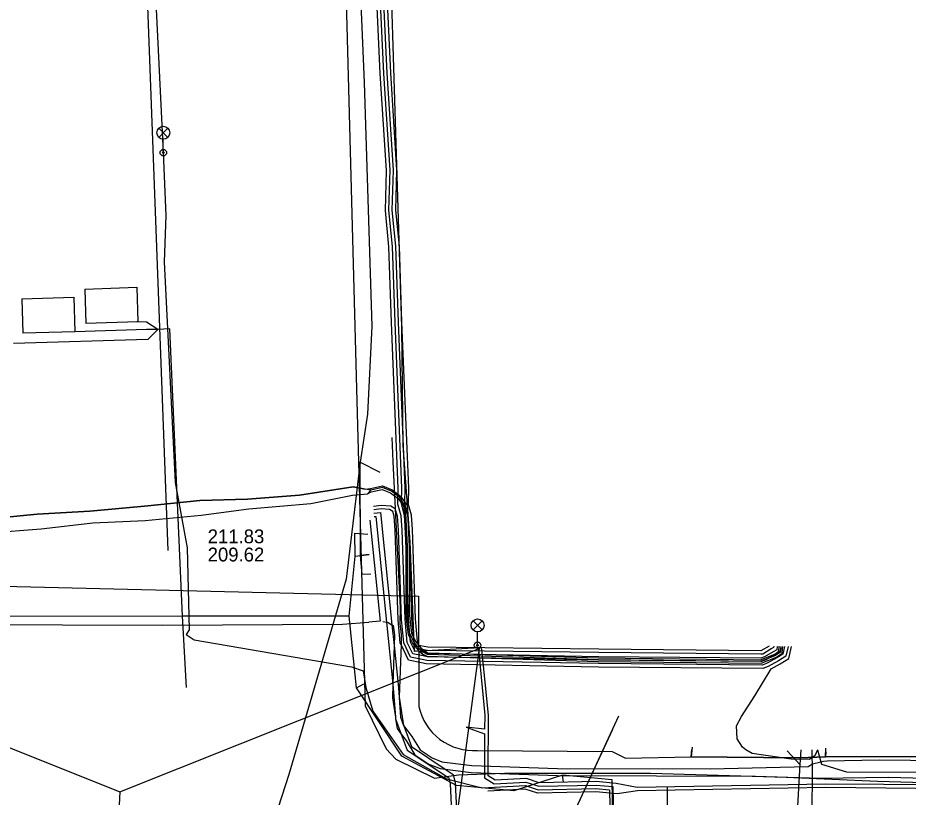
# Model space of a CAD drawing. Extents: x -596228 to -595156, y -1161235 to -1159373.
# Drawn here: x -595386.4 to -595334.9, y -1161026 to -1160980.9 of the extents above; entities that cross this region are included whole.
import ezdxf

# ---------------------------------------------------------------- set-up
doc = ezdxf.new("R2010")
doc.units = 0
for name, color, linetype in [('Vrstva 1', 7, 'Continuous'), ('Vrstva 12', 7, 'Continuous'), ('Vrstva 19', 7, 'Continuous'), ('Vrstva 33', 7, 'Continuous'), ('Vrstva 4', 7, 'Continuous'), ('Vrstva 42', 7, 'Continuous'), ('Vrstva 44', 7, 'Continuous'), ('Vrstva 54', 7, 'Continuous'), ('Vrstva 55', 7, 'Continuous'), ('Vrstva 58', 7, 'Continuous'), ('Vrstva 9', 7, 'Continuous')]:
    doc.layers.add(name, color=color, linetype=linetype)

msp = doc.modelspace()

# ---------------------------------------------------------------- linework, layer by layer
at = {"layer": 'Vrstva 1'}
for p, q in [((-595377.69, -1161011.68), (-595379.64, -1160959.52)), ((-595351.64, -1161021.26), (-595357.27, -1161033.42)), ((-595341.9, -1161023.27), (-595341.15, -1161024.06))]:
    msp.add_line(p, q, dxfattribs=at)
at = {"layer": 'Vrstva 12'}
for p in [(-595339.65, -1161023.32), (-595331.81, -1161023.6)]:
    msp.add_line(p, (-595339.67, -1161023.61), dxfattribs=at)
for points in [[(-595367.69, -1160963.36), (-595367.65, -1160963.76), (-595366.71, -1160969.68), (-595367.4, -1160979.92), (-595366.8, -1161002.33), (-595366.29, -1161020.66), (-595365.09, -1161023.16)], [(-595365.09, -1161023.16), (-595364.52, -1161023.76), (-595362.29, -1161024.86), (-595360.89, -1161024.66), (-595358.24, -1161024.57), (-595355.24, -1161024.57), (-595354.66, -1161024.57), (-595349.79, -1161024.56)], [(-595339.67, -1161023.61), (-595341.17, -1161023.67), (-595347.44, -1161023.62), (-595347.4, -1161023.2)], [(-595349.79, -1161024.56), (-595341.94, -1161024.8), (-595336.67, -1161025.03), (-595331.28, -1161025.18), (-595320.15, -1161025.06), (-595315.95, -1161025.06), (-595312.39, -1161025.22)]]:
    msp.add_lwpolyline(points, dxfattribs=at)
at = {"layer": 'Vrstva 19'}
for p, q in [((-595340.432, -1161024.484), (-595340.453, -1161023.206)), ((-595340.45, -1161026.84), (-595340.432, -1161024.484))]:
    msp.add_line(p, q, dxfattribs=at)
msp.add_lwpolyline([(-595348.81, -1161026.94), (-595348.817, -1161025.481), (-595348.816, -1161025.335)], dxfattribs=at)
at = {"layer": 'Vrstva 33'}
for p, q in [((-595378.235, -1160987.265), (-595377.705, -1160987.795)), ((-595378.235, -1160987.795), (-595377.705, -1160987.265)), ((-595377.97, -1160988.68), (-595377.97, -1160987.905)), ((-595360.059, -1161015.753), (-595359.529, -1161016.283)), ((-595360.059, -1161016.283), (-595359.529, -1161015.753)), ((-595359.794, -1161017.168), (-595359.794, -1161016.393))]:
    msp.add_line(p, q, dxfattribs=at)
for centre, radius in [((-595377.97, -1160987.53), 0.375), ((-595377.97, -1160988.68), 0.19), ((-595377.97, -1160988.68), 0.05), ((-595359.794, -1161016.018), 0.375), ((-595359.794, -1161017.168), 0.19), ((-595359.794, -1161017.168), 0.05)]:
    msp.add_circle(centre, radius, dxfattribs=at)
at = {"layer": 'Vrstva 42'}
for p, q in [((-595382.508, -1160996.565), (-595379.51, -1160996.467)), ((-595379.51, -1160996.467), (-595379.445, -1160998.466)), ((-595382.508, -1160996.565), (-595382.443, -1160998.564)), ((-595386.146, -1160997.129), (-595383.147, -1160997.04)), ((-595386.146, -1160997.129), (-595386.087, -1160999.128)), ((-595383.147, -1160997.04), (-595383.088, -1160999.039)), ((-595379.445, -1160998.466), (-595382.443, -1160998.564)), ((-595379.445, -1160998.466), (-595379.497, -1160998.468)), ((-595378.946, -1160998.48), (-595379.445, -1160998.466)), ((-595378.291, -1160998.903), (-595378.946, -1160998.48)), ((-595383.088, -1160999.039), (-595386.087, -1160999.128)), ((-595378.941, -1160998.912), (-595383.088, -1160999.039)), ((-595378.291, -1160998.903), (-595378.941, -1160998.912)), ((-595378.291, -1160998.903), (-595378.86, -1160999.477)), ((-595378.86, -1160999.477), (-595386.626, -1160999.714)), ((-595366.903, -1161010.68), (-595366.152, -1161010.751)), ((-595366.876, -1161012.022), (-595366.071, -1161011.924)), ((-595366.796, -1161019.625), (-595366.382, -1161019.402)), ((-595354.818, -1161025.09), (-595354.882, -1161024.669))]:
    msp.add_line(p, q, dxfattribs=at)
for points in [[(-595366.8, -1160974.13), (-595366.35, -1160984.63), (-595365.92, -1160998.71)], [(-595342.25, -1161017.23), (-595342.32, -1161017.55), (-595342.6, -1161017.72), (-595343.119, -1161018.012), (-595343.374, -1161018.11), (-595352.793, -1161018.03), (-595362.714, -1161017.84), (-595362.951, -1161017.786), (-595363.549, -1161017.671), (-595363.87, -1161016.999), (-595363.99, -1161015.666), (-595364.16, -1161010.505), (-595364.22, -1161009.677), (-595364.402, -1161009.01), (-595364.4, -1161008.922), (-595364.38, -1161008.093), (-595364.77, -1160998.501), (-595364.919, -1160994.12), (-595365.13, -1160992.021), (-595365.06, -1160989.705), (-595365.42, -1160984.107), (-595365.819, -1160975.572)], [(-595342.46, -1161017.23), (-595342.497, -1161017.424), (-595342.704, -1161017.549), (-595343.209, -1161017.832), (-595343.41, -1161017.91), (-595352.79, -1161017.83), (-595362.69, -1161017.64), (-595362.91, -1161017.59), (-595363.43, -1161017.49), (-595363.67, -1161016.981), (-595363.79, -1161015.654), (-595363.96, -1161010.495), (-595364.02, -1161009.663), (-595364.202, -1161008.99), (-595364.2, -1161008.927), (-595364.18, -1161008.091), (-595364.57, -1160998.494), (-595364.72, -1160994.107), (-595364.93, -1160992.014), (-595364.86, -1160989.702), (-595365.22, -1160984.096), (-595365.62, -1160975.551)], [(-595342.657, -1161017.221), (-595342.674, -1161017.297), (-595342.808, -1161017.378), (-595343.297, -1161017.679), (-595343.41, -1161017.69), (-595352.79, -1161017.59), (-595362.7, -1161017.47), (-595363.14, -1161017.39), (-595363.32, -1161017.35), (-595363.471, -1161016.963), (-595363.59, -1161015.642), (-595363.76, -1161010.484), (-595363.821, -1161009.648), (-595364.001, -1161008.97), (-595364, -1161008.933), (-595363.98, -1161008.089), (-595364.37, -1160998.486), (-595364.52, -1160994.093), (-595364.73, -1160992.006), (-595364.66, -1160989.698), (-595365.02, -1160984.084), (-595365.42, -1160975.529)], [(-595342.931, -1161017.218), (-595343.418, -1161017.49), (-595352.788, -1161017.39), (-595362.681, -1161017.27), (-595363.1, -1161017.194), (-595363.188, -1161017.174), (-595363.272, -1161016.945), (-595363.391, -1161015.629), (-595363.561, -1161010.474), (-595363.621, -1161009.634), (-595363.801, -1161008.965), (-595363.8, -1161008.938), (-595363.78, -1161008.088), (-595364.17, -1160998.479), (-595364.32, -1160994.08), (-595364.53, -1160991.999), (-595364.46, -1160989.695), (-595364.82, -1160984.073), (-595365.221, -1160975.508)], [(-595376.86, -1161015.49), (-595377.59, -1160998.875), (-595378.291, -1160998.903)], [(-595365.92, -1160998.71), (-595366.162, -1161003.793), (-595366.586, -1161006.586), (-595365.455, -1161007.152)], [(-595364.747, -1161005.146), (-595364.699, -1161006.547), (-595364.561, -1161009.281), (-595364.272, -1161014.986), (-595364.267, -1161015.003), (-595364.291, -1161015.907), (-595364.205, -1161016.543), (-595364.224, -1161017.126), (-595364.323, -1161020.175), (-595364.074, -1161021.801), (-595364.072, -1161021.814), (-595364.066, -1161021.822), (-595363.594, -1161022.451), (-595363.123, -1161023.221), (-595362.429, -1161023.683), (-595361.863, -1161023.905), (-595360.132, -1161024.126), (-595355.164, -1161024.292), (-595346.337, -1161024.321), (-595340.674, -1161024.173), (-595340.433, -1161024.029), (-595339.95, -1161023.906), (-595339.796, -1161023.867), (-595339.584, -1161023.858), (-595336.578, -1161023.801), (-595331.158, -1161023.852)], [(-595416.016, -1161006.14), (-595415.786, -1161006.15), (-595415.498, -1161006.235), (-595415.338, -1161006.482), (-595416.218, -1161013.623), (-595415.624, -1161014.085), (-595414.843, -1161014.3), (-595408.501, -1161014.826), (-595406.711, -1161015.033), (-595402.654, -1161015.522), (-595401.884, -1161015.7), (-595400.104, -1161016.11), (-595399.611, -1161016.162), (-595398.468, -1161016.036), (-595398.041, -1161016.049), (-595392.333, -1161016.113), (-595389.6, -1161015.959), (-595378.022, -1161015.998), (-595367.599, -1161015.944), (-595366.086, -1161015.828)], [(-595366.586, -1161006.586), (-595367.386, -1161013.351), (-595370.715, -1161024.634), (-595373.587, -1161033.521), (-595377.627, -1161052.858), (-595377.399, -1161059.852), (-595376.49, -1161070.471), (-595375.793, -1161073.227), (-595375.59, -1161076.931), (-595375.75, -1161078.662), (-595375.148, -1161080.228), (-595374.394, -1161084.227), (-595372.163, -1161100.132), (-595371.943, -1161102.902), (-595371.535, -1161104.379), (-595371.896, -1161105.915), (-595369.508, -1161121.937)], [(-595366.071, -1161011.923), (-595366.569, -1161011.967), (-595366.586, -1161006.586)], [(-595342.04, -1161017.23), (-595342.143, -1161017.676), (-595342.496, -1161017.891), (-595343.048, -1161018.199), (-595343.337, -1161018.311), (-595352.796, -1161018.23), (-595362.739, -1161018.039), (-595362.992, -1161017.982), (-595363.668, -1161017.852), (-595364.069, -1161017.017), (-595364.19, -1161015.678), (-595364.36, -1161010.516), (-595364.419, -1161009.692), (-595364.556, -1161009.284), (-595364.561, -1161009.281), (-595364.818, -1161009.122), (-595365.373, -1161009.08), (-595365.824, -1161009.141)], [(-595341.84, -1161017.24), (-595341.966, -1161017.803), (-595342.392, -1161018.062), (-595342.981, -1161018.387), (-595343.301, -1161018.511), (-595352.798, -1161018.43), (-595362.763, -1161018.239), (-595363.033, -1161018.177), (-595363.787, -1161018.032), (-595364.224, -1161017.126), (-595364.268, -1161017.035), (-595364.389, -1161015.691), (-595364.559, -1161010.526), (-595364.619, -1161009.706), (-595364.688, -1161009.437), (-595364.882, -1161009.318), (-595365.367, -1161009.281), (-595365.796, -1161009.339)], [(-595365.795, -1161009.521), (-595365.41, -1161009.481), (-595364.748, -1161015.979), (-595364.625, -1161017.182), (-595364.376, -1161019.63), (-595364.25, -1161021.332), (-595364.074, -1161021.801), (-595364.066, -1161021.822), (-595363.614, -1161023.028), (-595361.661, -1161024.334), (-595361.201, -1161024.641), (-595361.086, -1161025.129), (-595360.52, -1161036.864)], [(-595365.784, -1161009.728), (-595365.688, -1161009.715), (-595365.065, -1161015.825), (-595364.699, -1161019.418), (-595364.675, -1161019.656), (-595364.551, -1161021.332), (-595364.546, -1161021.397), (-595364.537, -1161021.421), (-595364.207, -1161022.3), (-595363.861, -1161023.224), (-595361.466, -1161024.825), (-595361.384, -1161025.171), (-595360.819, -1161036.892), (-595360.775, -1161037.203), (-595360.638, -1161038.158), (-595360.969, -1161038.62), (-595360.909, -1161041.211), (-595360.581, -1161041.493), (-595360.883, -1161041.682), (-595361.086, -1161041.994), (-595361.638, -1161042.839), (-595361.661, -1161043.925)], [(-595366.021, -1161009.937), (-595365.42, -1161015.773), (-595366.086, -1161015.828)], [(-595367.228, -1161015.48), (-595366.876, -1161012.022), (-595366.903, -1161010.68)], [(-595365.975, -1161013.059), (-595366.474, -1161013.078), (-595366.569, -1161011.967)], [(-595376.86, -1161015.49), (-595390.719, -1161015.495), (-595390.365, -1161019.849), (-595393.85, -1161019.384)], [(-595361.473, -1161063.225), (-595363.291, -1161048.247), (-595365.169, -1161043.721), (-595364.714, -1161042.286), (-595363.329, -1161039.242), (-595360.169, -1161037.172), (-595354.954, -1161037.05), (-595351.811, -1161036.261), (-595352.018, -1161024.947), (-595354.882, -1161024.669), (-595357.697, -1161025.585), (-595361.017, -1161025.278), (-595364.184, -1161023.581), (-595366.796, -1161019.625), (-595367.228, -1161015.48), (-595376.86, -1161015.49)], [(-595376.621, -1161019.601), (-595376.846, -1161015.811), (-595376.86, -1161015.49)], [(-595365.277, -1161015.785), (-595365.28, -1161015.785), (-595365.065, -1161015.825), (-595364.966, -1161015.844), (-595364.748, -1161015.979), (-595364.679, -1161016.022), (-595364.605, -1161016.563), (-595364.625, -1161017.182), (-595364.699, -1161019.418), (-595364.725, -1161020.199), (-595364.551, -1161021.332), (-595364.537, -1161021.421), (-595364.452, -1161021.974), (-595364.207, -1161022.3), (-595363.926, -1161022.675), (-595363.419, -1161023.505), (-595362.615, -1161024.039), (-595361.963, -1161024.295), (-595361.661, -1161024.334), (-595360.164, -1161024.526), (-595355.172, -1161024.692), (-595343.724, -1161024.729), (-595339.96, -1161024.845), (-595336.03, -1161024.802), (-595331.08, -1161024.928)], [(-595340.14, -1161023.21), (-595340.3, -1161023.57), (-595340.62, -1161023.77), (-595341.65, -1161023.75), (-595343.12, -1161023.54), (-595343.91, -1161023.43), (-595344.28, -1161023.22), (-595344.47, -1161023.05), (-595344.78, -1161022.57), (-595344.82, -1161021.82), (-595344.53, -1161021.28), (-595343.76, -1161020.09), (-595342.823, -1161018.523), (-595342.289, -1161018.233), (-595341.789, -1161017.929), (-595341.64, -1161017.23)], [(-595340.14, -1161023.21), (-595339.95, -1161023.906), (-595339.913, -1161024.04), (-595338.454, -1161024.482), (-595333.673, -1161024.5)]]:
    msp.add_lwpolyline(points, dxfattribs=at)
at = {"layer": 'Vrstva 44'}
for points in [[(-595388.23, -1161009.87), (-595385.26, -1161009.59), (-595382.23, -1161009.41), (-595379.05, -1161009.13), (-595375.86, -1161008.8), (-595373.1, -1161008.71), (-595370.1, -1161008.49), (-595367, -1161008), (-595366.3, -1161008.14), (-595365.992, -1161008.102), (-595365.291, -1161007.946), (-595364.73, -1161008.172), (-595364.247, -1161008.54), (-595364.018, -1161008.873), (-595363.872, -1161009.087), (-595363.75, -1161011.447), (-595363.75, -1161015.227), (-595363.72, -1161015.641), (-595363.623, -1161016.48), (-595363.367, -1161016.974), (-595363.069, -1161017.319), (-595362.853, -1161017.507), (-595362.674, -1161017.601), (-595352.808, -1161017.9), (-595343.429, -1161018), (-595342.608, -1161017.672), (-595342.375, -1161017.505), (-595342.35, -1161017.221)], [(-595388.04, -1161010.66), (-595385.04, -1161010.43), (-595382.04, -1161010.08), (-595379.02, -1161009.96), (-595375.79, -1161009.64), (-595373.03, -1161009.27), (-595369.44, -1161008.96), (-595367.02, -1161008.48), (-595366.17, -1161008.41), (-595365.948, -1161008.298), (-595365.308, -1161008.154), (-595364.83, -1161008.348), (-595364.393, -1161008.68), (-595364.182, -1161008.987), (-595364.068, -1161009.153), (-595363.95, -1161011.453), (-595363.95, -1161015.233), (-595363.92, -1161015.659), (-595363.817, -1161016.54), (-595363.533, -1161017.086), (-595363.211, -1161017.461), (-595362.967, -1161017.673), (-595362.726, -1161017.799), (-595352.812, -1161018.1), (-595343.391, -1161018.2), (-595342.512, -1161017.848), (-595342.185, -1161017.615), (-595342.15, -1161017.23)]]:
    msp.add_lwpolyline(points, dxfattribs=at)
at = {"layer": 'Vrstva 54'}
for p, q in [((-595401.19, -1161017.33), (-595380.48, -1161025.65)), ((-595380.48, -1161025.65), (-595359.71, -1161017.36)), ((-595359.71, -1161017.36), (-595363.59, -1161046.43)), ((-595380.48, -1161025.65), (-595381, -1161034.68))]:
    msp.add_line(p, q, dxfattribs=at)
at = {"layer": 'Vrstva 55'}
for points in [[(-595379.423, -1160959.056), (-595377.97, -1160988.68)], [(-595364.17, -1160998.78), (-595365.24, -1160964.37), (-595366.535, -1160960.59), (-595368.38, -1160960.57)], [(-595377.97, -1160988.68), (-595377.83, -1160992.32), (-595377.92, -1160994.99), (-595377.28, -1161007.76), (-595376.59, -1161011.53), (-595376.47, -1161016.28), (-595376.64, -1161016.55), (-595376.18, -1161016.85), (-595367.078, -1161018.41), (-595366.41, -1161018.65), (-595366.25, -1161019.6), (-595365.86, -1161020.97), (-595364.1, -1161023.49), (-595361.6, -1161024.89), (-595359.535, -1161025.416), (-595357.024, -1161025.283), (-595356.29, -1161025.52), (-595352.948, -1161025.45), (-595352.166, -1161025.522), (-595351.96, -1161035.918)], [(-595359.798, -1161017.28), (-595360.017, -1161017.33), (-595363.45, -1161017.52), (-595363.7, -1161011.18), (-595364.09, -1161005.61), (-595364.17, -1160998.78)], [(-595322.855, -1161025.304), (-595339.651, -1161025.2), (-595350.571, -1161025.389), (-595351.773, -1161025.155), (-595352.933, -1161025.05), (-595356.23, -1161025.119), (-595356.972, -1161024.879), (-595358.78, -1161024.975), (-595359.188, -1161024.716), (-595359.17, -1161021.2), (-595359.54, -1161017.4), (-595359.63, -1161017.23), (-595359.74, -1161017.42), (-595359.37, -1161021.21), (-595359.389, -1161022.011), (-595360.462, -1161021.911), (-595359.389, -1161022.289), (-595359.389, -1161022.507), (-595359.388, -1161024.826)], [(-595359.388, -1161024.826), (-595358.833, -1161025.178), (-595356.998, -1161025.081), (-595356.26, -1161025.32), (-595352.94, -1161025.25), (-595351.97, -1161025.338), (-595351.76, -1161035.922), (-595351.811, -1161036.676), (-595351.96, -1161037.24), (-595353.814, -1161037.49), (-595359.483, -1161037.39), (-595361.37, -1161037.703), (-595361.872, -1161038.242), (-595363.291, -1161042.618), (-595363.31, -1161043.074), (-595360.381, -1161042.574)], [(-595330.99, -1161025.48), (-595339.65, -1161025.4), (-595350.553, -1161025.584), (-595351.722, -1161025.764), (-595352.955, -1161025.65), (-595356.319, -1161025.721), (-595357.05, -1161025.485), (-595359.202, -1161025.599)]]:
    msp.add_lwpolyline(points, dxfattribs=at)
at = {"layer": 'Vrstva 58'}
for p, q in [((-595363.21, -1161014.329), (-595363.2, -1161020.704)), ((-595359.796, -1161023.249), (-595352.003, -1161023.312)), ((-595347.394, -1161023.053), (-595347.444, -1161023.617)), ((-595339.674, -1161023.614), (-595339.645, -1161023.117)), ((-595347.444, -1161023.617), (-595341.173, -1161023.667)), ((-595341.173, -1161023.667), (-595339.674, -1161023.614))]:
    msp.add_line(p, q, dxfattribs=at)
for points in [[(-595365.97, -1161008.2), (-595366.3, -1161008.14), (-595367, -1161008), (-595370.1, -1161008.49), (-595373.1, -1161008.71), (-595375.86, -1161008.8), (-595379.05, -1161009.13), (-595382.23, -1161009.41), (-595385.26, -1161009.59), (-595388.23, -1161009.87), (-595391.04, -1161010.1), (-595393.75, -1161010.34), (-595395.83, -1161010.84), (-595397.4, -1161011.06), (-595398.6, -1161011.19), (-595399.23, -1161011.35)], [(-595399.23, -1161011.35), (-595398.58, -1161011.45), (-595397.36, -1161011.46), (-595395.79, -1161011.33), (-595393.38, -1161011.29), (-595390.8, -1161010.98), (-595388.04, -1161010.66), (-595385.04, -1161010.43), (-595382.04, -1161010.08), (-595379.02, -1161009.96), (-595375.79, -1161009.64), (-595373.03, -1161009.27), (-595369.44, -1161008.96), (-595367.02, -1161008.48), (-595366.17, -1161008.41), (-595365.97, -1161008.2)], [(-595342.25, -1161017.23), (-595342.28, -1161017.56), (-595342.56, -1161017.76), (-595343.41, -1161018.1), (-595352.81, -1161018), (-595362.7, -1161017.7), (-595362.91, -1161017.59), (-595363.14, -1161017.39), (-595363.45, -1161017.03), (-595363.72, -1161016.51), (-595363.82, -1161015.65), (-595363.85, -1161015.23), (-595363.85, -1161011.45), (-595363.97, -1161009.12), (-595364.1, -1161008.93), (-595364.32, -1161008.61), (-595364.78, -1161008.26), (-595365.3, -1161008.05), (-595365.97, -1161008.2)], [(-595439.94, -1161017.52), (-595430.31, -1161017.16), (-595421.16, -1161017.02), (-595417.17, -1161016.96), (-595415.97, -1161016.72), (-595415.21, -1161016.07), (-595414.843, -1161012.766), (-595411.172, -1161012.884), (-595405.274, -1161013.459), (-595402.491, -1161013.383), (-595363.21, -1161014.329), (-595363.2, -1161020.704)], [(-595414.843, -1161012.766), (-595411.172, -1161012.884), (-595405.274, -1161013.459), (-595402.491, -1161013.383), (-595363.21, -1161014.329)], [(-595363.2, -1161020.704), (-595363.125, -1161020.984), (-595363.026, -1161021.255), (-595362.903, -1161021.517), (-595362.757, -1161021.767), (-595362.589, -1161022.003), (-595362.401, -1161022.223), (-595362.195, -1161022.426), (-595361.971, -1161022.609), (-595361.732, -1161022.772), (-595361.479, -1161022.913), (-595361.215, -1161023.031), (-595360.941, -1161023.124), (-595360.66, -1161023.194), (-595360.374, -1161023.238), (-595360.085, -1161023.256), (-595359.796, -1161023.249)], [(-595359.796, -1161023.249), (-595352.003, -1161023.312), (-595351.242, -1161023.691), (-595347.444, -1161023.617), (-595341.173, -1161023.667), (-595339.674, -1161023.614), (-595331.814, -1161023.602)], [(-595339.674, -1161023.614), (-595331.814, -1161023.602), (-595331.798, -1161023.247)], [(-595352.003, -1161023.312), (-595351.242, -1161023.691), (-595347.444, -1161023.617)]]:
    msp.add_lwpolyline(points, dxfattribs=at)
at = {"layer": 'Vrstva 9'}
msp.add_line((-595352, -1161022.034), (-595357.27, -1161033.42), dxfattribs=at)
msp.add_lwpolyline([(-595341.102, -1161023.215), (-595341.15, -1161024.06), (-595341.671, -1161033.414)], dxfattribs=at)

# ---------------------------------------------------------------- texts
at = {"layer": 'Vrstva 4'}
for s, p in [('211.83', (-595375.404, -1161011.27)), ('209.62', (-595375.404, -1161012.32))]:
    msp.add_text(s, height=0.8, dxfattribs=at).set_placement(p)

doc.saveas('drawing.dxf')
